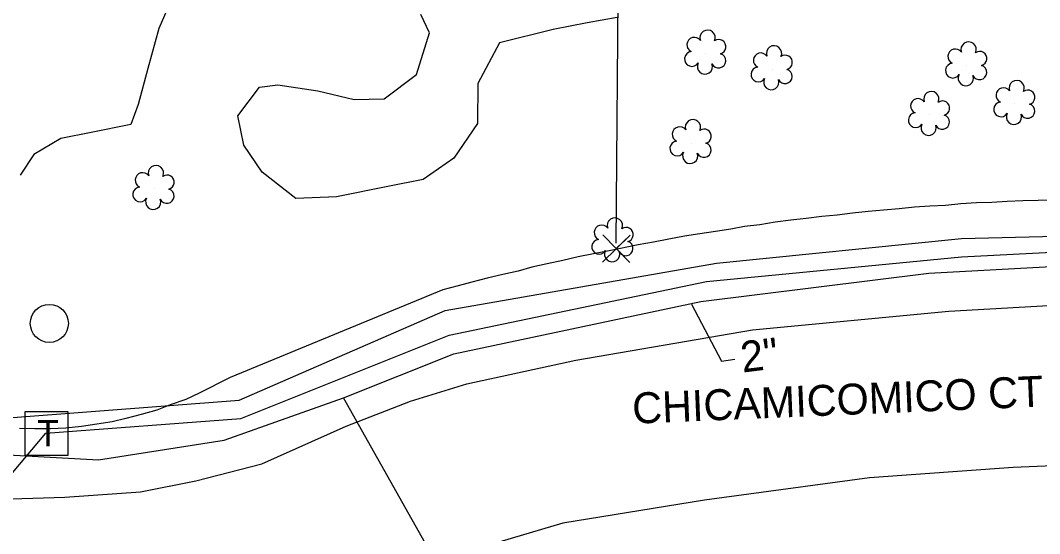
# Model space of a CAD drawing. Extents: x 3040896 to 3051146, y 687568 to 732976.
# Drawn here: x 3049457.3 to 3049589.1, y 694102.3 to 694168.7 of the extents above; entities that cross this region are included whole.
import ezdxf

# ---------------------------------------------------------------- set-up
doc = ezdxf.new("R2010")
doc.units = 0
for name, color, linetype in [('Exist Property Corner CELL', 7, 'Continuous'), ('Exist Property Line', 7, 'Continuous'), ('Exist Roads EOP', 7, 'Continuous'), ('Exist Roads EOP Text', 7, 'Continuous'), ('Exist Utilities Other Pole CELL', 7, 'Continuous'), ('Exist Utilities Telephone Pedestal CELL', 7, 'Continuous'), ('Exist Utilities Telephone UG Cable', 7, 'Continuous'), ('Exist Utilities TV UG Cable', 7, 'Continuous'), ('Exist Utilities Water UG Line', 7, 'Continuous'), ('Exist Utilities Water UG Line Leader', 7, 'Continuous'), ('Exist Utilities Water UG Line Text', 7, 'Continuous'), ('Exist Vegetation Shrub CELL', 7, 'Continuous'), ('Exist Vegetation Woods Line', 7, 'Continuous'), ('Old_Level_13', 7, 'Continuous')]:
    doc.layers.add(name, color=color, linetype=linetype)

msp = doc.modelspace()

# ---------------------------------------------------------------- linework, layer by layer
at = {"layer": 'Exist Property Corner CELL'}
msp.add_line((3049534.39, 694139.15), (3049534.39, 694139.15), dxfattribs=at)
msp.add_lwpolyline([(3049532.63, 694140.93), (3049536.14, 694137.37), (3049534.39, 694139.15), (3049536.17, 694140.9), (3049532.6, 694137.39)], dxfattribs=at)
at = {"layer": 'Exist Property Line'}
msp.add_line((3049534.39, 694139.88), (3049536.46, 694420.18), dxfattribs=at)
at = {"layer": 'Exist Roads EOP'}
for points in [[(3049453.33, 694106.71), (3049463.07, 694107), (3049472.85, 694107.68), (3049480.01, 694109.1), (3049488.56, 694111.32), (3049499.47, 694116.18), (3049507.75, 694119.4), (3049515.06, 694121.68), (3049529.14, 694124.74), (3049552.01, 694128.65), (3049577.41, 694131.05), (3049609.98, 694132.9), (3049623.89, 694133.12), (3049628.1, 694134), (3049634.92, 694136.34), (3049644.23, 694140.94), (3049651.54, 694146.39), (3049654.35, 694149.23), (3049656.47, 694154.67), (3049658.79, 694160.76), (3049661.07, 694165.59), (3049661.85, 694167.24)], [(3049716.56, 694122.36), (3049712.59, 694118.9), (3049707.37, 694115.95), (3049699.59, 694112.22), (3049693.71, 694110.45), (3049686.44, 694110.04), (3049669.84, 694110.4), (3049649.98, 694111.33), (3049634.76, 694111.51), (3049609.48, 694111.82), (3049585.73, 694110.83), (3049567.15, 694109.49), (3049545.79, 694106.61), (3049527.47, 694103.61), (3049518.05, 694100.84), (3049507.59, 694096.28), (3049497.81, 694090.95), (3049487.9, 694081.62), (3049481.17, 694074.53), (3049477.94, 694068.93), (3049475.24, 694061.1), (3049473.07, 694052.72), (3049471.85, 694044.77)]]:
    msp.add_lwpolyline(points, dxfattribs=at)
at = {"layer": 'Exist Utilities Other Pole CELL'}
msp.add_circle((3049461.06, 694129.48), 2.46, dxfattribs=at)
at = {"layer": 'Exist Utilities Telephone Pedestal CELL'}
msp.add_line((3049460.62, 694115.27), (3049460.62, 694115.27), dxfattribs=at)
msp.add_lwpolyline([(3049457.89, 694112.45), (3049463.49, 694112.45), (3049463.49, 694118.04), (3049457.89, 694118.04), (3049457.89, 694112.45)], dxfattribs=at)
at = {"layer": 'Exist Utilities Telephone UG Cable'}
for points in [[(3049460.62, 694115.27), (3049485.81, 694117.16), (3049512.76, 694127.94), (3049546.06, 694134.91), (3049579.03, 694138.08), (3049615.81, 694139.99), (3049615.26, 694145.39)], [(3049383.76, 693316.92), (3049378.37, 693331.83), (3049375.2, 693367.34), (3049377.42, 693461.19), (3049370.49, 693463.44), (3049378.05, 693464.68), (3049383.76, 693640.33), (3049386.61, 693731.65), (3049378.64, 693733.75), (3049386.61, 693735.45), (3049390.1, 693802.35), (3049395.17, 693833.74), (3049405.64, 693860.06), (3049424.98, 693915.23), (3049417.8, 693919.36), (3049426.24, 693918.08), (3049445.27, 693989.1), (3049450.34, 694037.61), (3049454.46, 694108), (3049460.62, 694115.27)]]:
    msp.add_lwpolyline(points, dxfattribs=at)
at = {"layer": 'Exist Utilities TV UG Cable'}
msp.add_lwpolyline([(3049446.71, 694116.57), (3049485.61, 694119.53), (3049512.24, 694131.15), (3049547.33, 694137.28), (3049579.03, 694140.45), (3049612.22, 694141.3), (3049612.54, 694145.92), (3049614.55, 694141.3), (3049630.19, 694142.99), (3049642.66, 694149.75), (3049651.33, 694159.69), (3049659.57, 694176.39), (3049670.56, 694185.69), (3049686.2, 694191.39), (3049701.21, 694190.13), (3049716.85, 694184.21), (3049720.13, 694186.33)], dxfattribs=at)
at = {"layer": 'Exist Utilities Water UG Line'}
for points in [[(3049439.17, 693868.02), (3049460.93, 693929.56), (3049466.87, 693954.26), (3049472.36, 693988.56), (3049478.6, 694058.55), (3049486.63, 694077.79), (3049500.37, 694089.2), (3049512.42, 694096.18), (3049499.11, 694119.85), (3049513.38, 694125.56), (3049545.34, 694132.33), (3049574.81, 694135.99), (3049612.01, 694138.02), (3049630.92, 694139.85), (3049644.33, 694146.56), (3049651.65, 694156.52), (3049661.41, 694175.22), (3049672.79, 694182.74), (3049686.82, 694188.44), (3049699.01, 694187.83), (3049715.48, 694182.54), (3049725.36, 694173.4), (3049730.47, 694163.6), (3049731.96, 694155.59)], [(3049342.2, 694087.66), (3049335.74, 694100.79), (3049335.13, 694122.44), (3049340.31, 694137.69), (3049352.81, 694149.27), (3049375.99, 694155.68), (3049391.84, 694151.41), (3049403.12, 694141.95), (3049414.71, 694126.1), (3049425.69, 694116.95), (3049446.36, 694112.97), (3049467.4, 694111.82), (3049483.67, 694114.36), (3049499.11, 694119.85)]]:
    msp.add_lwpolyline(points, dxfattribs=at)
at = {"layer": 'Exist Utilities Water UG Line Leader'}
msp.add_lwpolyline([(3049544.1, 694131.95), (3049547.98, 694124.6), (3049549.73, 694124.85)], dxfattribs=at)
at = {"layer": 'Exist Vegetation Shrub CELL'}
for p, q in [((3049545.97, 694164.4), (3049545.97, 694164.4)), ((3049579.72, 694162.88), (3049579.72, 694162.88)), ((3049554.56, 694162.38), (3049554.56, 694162.38)), ((3049585.94, 694157.88), (3049585.94, 694157.88)), ((3049574.91, 694156.47), (3049574.91, 694156.47)), ((3049544.07, 694152.82), (3049544.07, 694152.82)), ((3049474.61, 694146.88), (3049474.61, 694146.88)), ((3049533.98, 694140.1), (3049533.98, 694140.1))]:
    msp.add_line(p, q, dxfattribs=at)
for centre, radius, start, end in [((3049544.49, 694165.52), 0.968, 35.8908, 245.4216), ((3049546.2, 694166.44), 0.99, 334.8391, 200.4717), ((3049547.64, 694165.27), 0.929, 284.4567, 126.0861), ((3049554.79, 694164.42), 0.99, 334.8391, 200.4717), ((3049579.95, 694164.92), 0.99, 334.8391, 200.4717), ((3049544.17, 694163.69), 0.955, 95.1099, 327.9534), ((3049547.61, 694163.47), 0.937, 204.9913, 73.4601), ((3049553.08, 694163.5), 0.968, 35.8908, 245.4216), ((3049556.23, 694163.25), 0.929, 284.4567, 126.0861), ((3049578.24, 694164.01), 0.968, 35.8908, 245.4216), ((3049581.39, 694163.75), 0.929, 284.4567, 126.0861), ((3049545.84, 694162.71), 0.984, 151.2797, 21.387), ((3049552.76, 694161.67), 0.955, 95.1099, 327.9534), ((3049577.92, 694162.18), 0.955, 95.1099, 327.9534), ((3049581.36, 694161.95), 0.937, 204.9913, 73.4601), ((3049556.2, 694161.45), 0.937, 204.9913, 73.4601), ((3049579.59, 694161.2), 0.984, 151.2797, 21.387), ((3049554.43, 694160.69), 0.984, 151.2797, 21.387), ((3049584.46, 694159), 0.968, 35.8908, 245.4216), ((3049586.17, 694159.92), 0.99, 334.8391, 200.4717), ((3049573.42, 694157.59), 0.968, 35.8908, 245.4216), ((3049575.13, 694158.51), 0.99, 334.8391, 200.4717), ((3049587.61, 694158.74), 0.929, 284.4567, 126.0861), ((3049576.58, 694157.33), 0.929, 284.4567, 126.0861), ((3049584.14, 694157.17), 0.955, 95.1099, 327.9534), ((3049587.58, 694156.95), 0.937, 204.9913, 73.4601), ((3049573.11, 694155.76), 0.955, 95.1099, 327.9534), ((3049576.54, 694155.54), 0.937, 204.9913, 73.4601), ((3049585.81, 694156.19), 0.984, 151.2797, 21.387), ((3049542.59, 694153.95), 0.968, 35.8908, 245.4216), ((3049544.3, 694154.86), 0.99, 334.8391, 200.4717), ((3049545.74, 694153.69), 0.929, 284.4567, 126.0861), ((3049574.78, 694154.78), 0.984, 151.2797, 21.387), ((3049542.27, 694152.12), 0.955, 95.1099, 327.9534), ((3049545.71, 694151.9), 0.937, 204.9913, 73.4601), ((3049543.94, 694151.14), 0.984, 151.2797, 21.387), ((3049474.84, 694148.92), 0.99, 334.8391, 200.4717), ((3049473.13, 694148.01), 0.968, 35.8908, 245.4216), ((3049476.29, 694147.75), 0.929, 284.4567, 126.0861), ((3049472.81, 694146.17), 0.955, 95.1099, 327.9534), ((3049476.25, 694145.95), 0.937, 204.9913, 73.4601), ((3049474.49, 694145.2), 0.984, 151.2797, 21.387), ((3049534.2, 694142.14), 0.99, 334.8391, 200.4717), ((3049532.49, 694141.23), 0.968, 35.8908, 245.4216), ((3049535.65, 694140.97), 0.929, 284.4567, 126.0861), ((3049532.17, 694139.4), 0.955, 95.1099, 327.9534), ((3049533.85, 694138.42), 0.984, 151.2797, 21.387), ((3049535.61, 694139.17), 0.937, 204.9913, 73.4601)]:
    msp.add_arc(centre, radius, start, end, dxfattribs=at)
at = {"layer": 'Exist Vegetation Woods Line'}
for points in [[(3049477.71, 694173.41), (3049475.23, 694167.64), (3049473.8, 694162.45), (3049472.57, 694157.78), (3049471.62, 694155.21), (3049466.46, 694154.19), (3049462.53, 694153.41), (3049459.05, 694151.33), (3049457.31, 694148.66)], [(3049534.49, 694169.05), (3049530.62, 694168.37), (3049526.2, 694167.49), (3049519.3, 694165.77), (3049516.48, 694160.53), (3049516.42, 694155.34), (3049513.39, 694150.86), (3049509.4, 694148.09), (3049504.84, 694147.18), (3049498.21, 694145.86), (3049492.96, 694145.66), (3049488.58, 694149.04), (3049486.2, 694152.54), (3049485.45, 694156.32), (3049488.25, 694160.06), (3049490.62, 694160.33), (3049495.77, 694159.58), (3049500.47, 694158.46), (3049504.35, 694158.52), (3049508.53, 694161.7), (3049510.21, 694167.06), (3049509.12, 694169.46)]]:
    msp.add_lwpolyline(points, dxfattribs=at)
at = {"layer": 'Old_Level_13'}
for points in [[(3049590.95, 694145.44), (3049588.95, 694145.38), (3049586.95, 694145.32), (3049584.95, 694145.25), (3049582.95, 694145.13), (3049580.95, 694145.07), (3049578.95, 694144.94), (3049576.95, 694144.75), (3049574.95, 694144.63), (3049572.95, 694144.5), (3049570.95, 694144.32), (3049568.95, 694144.13), (3049566.95, 694143.94), (3049564.95, 694143.75), (3049562.95, 694143.5), (3049560.95, 694143.32), (3049558.95, 694143.07), (3049556.95, 694142.82), (3049554.95, 694142.57), (3049552.95, 694142.25), (3049550.95, 694142), (3049549.2, 694141.69), (3049547.2, 694141.38), (3049545.2, 694141.07), (3049543.2, 694140.75), (3049541.2, 694140.38), (3049539.2, 694140), (3049537.2, 694139.63), (3049534.7, 694139.13)], [(3049590.95, 694145.44), (3049588.95, 694145.38), (3049586.95, 694145.32), (3049584.95, 694145.25), (3049582.95, 694145.13), (3049580.95, 694145.07), (3049578.95, 694144.94), (3049576.95, 694144.75), (3049574.95, 694144.63), (3049572.95, 694144.5), (3049570.95, 694144.32), (3049568.95, 694144.13), (3049566.95, 694143.94), (3049564.95, 694143.75), (3049562.95, 694143.5), (3049560.95, 694143.32), (3049558.95, 694143.07), (3049556.95, 694142.82), (3049554.95, 694142.57), (3049552.95, 694142.25), (3049550.95, 694142), (3049549.2, 694141.69), (3049547.2, 694141.38), (3049545.2, 694141.07), (3049543.2, 694140.75), (3049541.2, 694140.38), (3049539.2, 694140), (3049537.2, 694139.63), (3049534.7, 694139.13)], [(3049534.7, 694139.13), (3049533.45, 694138.88), (3049531.45, 694138.5), (3049529.45, 694138.07), (3049527.45, 694137.63), (3049525.45, 694137.19), (3049523.45, 694136.75), (3049521.7, 694136.25), (3049519.7, 694135.82), (3049517.7, 694135.32), (3049515.7, 694134.82), (3049513.95, 694134.32), (3049511.95, 694133.82), (3049484.45, 694122.5), (3049480.45, 694120.44), (3049478.7, 694119.63), (3049476.7, 694118.94), (3049474.95, 694118.25), (3049472.95, 694117.69), (3049470.95, 694117.19), (3049469.2, 694116.75), (3049467.2, 694116.44), (3049465.2, 694116.13), (3049463.2, 694115.94), (3049461.2, 694115.82), (3049459.2, 694115.82), (3049457.2, 694115.88)], [(3049534.7, 694139.13), (3049533.45, 694138.88), (3049531.45, 694138.5), (3049529.45, 694138.07), (3049527.45, 694137.63), (3049525.45, 694137.19), (3049523.45, 694136.75), (3049521.7, 694136.25), (3049519.7, 694135.82), (3049517.7, 694135.32), (3049515.7, 694134.82), (3049513.95, 694134.32), (3049511.95, 694133.82), (3049484.45, 694122.5), (3049480.45, 694120.44), (3049478.7, 694119.63), (3049476.7, 694118.94), (3049474.95, 694118.25), (3049472.95, 694117.69), (3049470.95, 694117.19), (3049469.2, 694116.75), (3049467.2, 694116.44), (3049465.2, 694116.13), (3049463.2, 694115.94), (3049461.2, 694115.82), (3049459.2, 694115.82), (3049457.2, 694115.88)]]:
    msp.add_lwpolyline(points, dxfattribs=at)

# ---------------------------------------------------------------- texts
at = {"layer": 'Exist Roads EOP Text'}
msp.add_text('CHICAMICOMICO CT    BST', height=4, rotation=2.406, dxfattribs=at).set_placement((3049536.53, 694116.49))
at = {"layer": 'Exist Utilities Telephone Pedestal CELL'}
msp.add_text('T', height=3.42, dxfattribs=at).set_placement((3049459.49, 694113.56))
at = {"layer": 'Exist Utilities Water UG Line Text'}
msp.add_text('2"', height=4, rotation=7.0764, dxfattribs=at).set_placement((3049550.71, 694123.11))

doc.saveas('drawing.dxf')
